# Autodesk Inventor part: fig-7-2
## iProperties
Created: 2004-05
Part Number: fig-7-2
Document SubType Name: Modeling
Designer: CADCIM Technologies
Manufacturer: Standard
Standards Organization: Custom
Author: CADCIM Technologies
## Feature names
1. Sweep4
